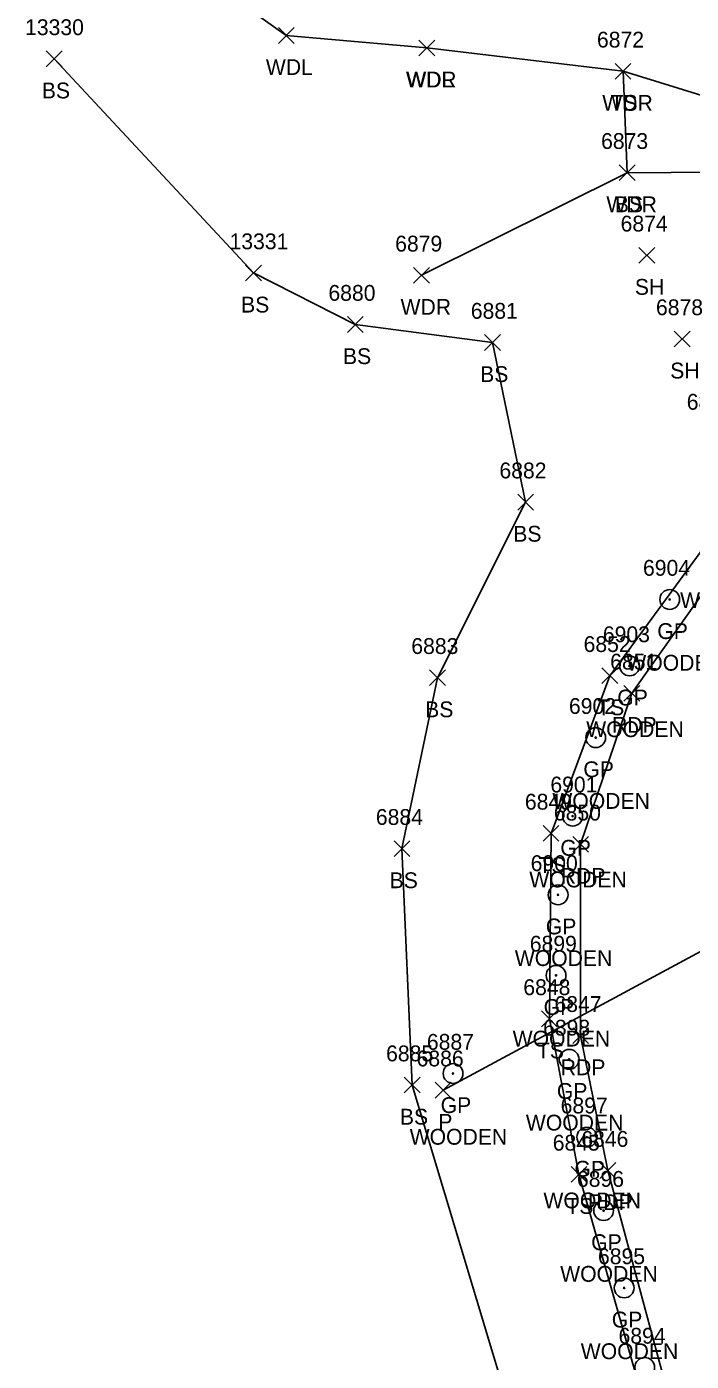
# Model space of a CAD drawing. Extents: x 1769141 to 1770817, y 735471 to 742405.
# Drawn here: x 1770005.7 to 1770089.7, y 740809.3 to 740978 of the extents above; entities that cross this region are included whole.
import ezdxf

# ---------------------------------------------------------------- set-up
doc = ezdxf.new("R2010")
doc.units = 0
for name, color, linetype in [('D_A', 7, 'Continuous'), ('D_I', 7, 'Continuous'), ('D_TIC', 7, 'Continuous'), ('DCP', 7, 'Continuous'), ('L_A', 7, 'Continuous'), ('L_I', 7, 'Continuous'), ('L_TIC', 7, 'Continuous'), ('LAWA', 7, 'Continuous'), ('LELB', 7, 'Continuous'), ('P_A', 7, 'Continuous'), ('P_I', 7, 'Continuous'), ('P_TIC', 7, 'Continuous'), ('PET', 7, 'Continuous'), ('R_A', 7, 'Continuous'), ('R_C', 7, 'Continuous'), ('R_I', 7, 'Continuous'), ('RGP', 7, 'Continuous')]:
    doc.layers.add(name, color=color, linetype=linetype)

msp = doc.modelspace()

# ---------------------------------------------------------------- linework, layer by layer
at = {"layer": 'D_TIC'}
for points in [[(1770057.36, 740842.55), (1770059.36, 740844.55)], [(1770059.36, 740842.55), (1770057.36, 740844.55)]]:
    msp.add_lwpolyline(points, dxfattribs=at)
at = {"layer": 'DCP'}
msp.add_lwpolyline([(1770123.5, 740878.66), (1770058.36, 740843.55)], dxfattribs=at)
at = {"layer": 'L_TIC'}
for points in [[(1770037.53, 740975.89), (1770039.53, 740977.89)], [(1770039.53, 740975.89), (1770037.53, 740977.89)], [(1770055.29, 740974.31), (1770057.29, 740976.31)], [(1770057.29, 740974.31), (1770055.29, 740976.31)], [(1770055.29, 740974.31), (1770057.29, 740976.31)], [(1770057.29, 740974.31), (1770055.29, 740976.31)], [(1770008.18, 740972.93), (1770010.18, 740974.93)], [(1770010.18, 740972.93), (1770008.18, 740974.93)], [(1770080.1, 740971.36), (1770082.1, 740973.36)], [(1770082.1, 740971.36), (1770080.1, 740973.36)], [(1770080.1, 740971.36), (1770082.1, 740973.36)], [(1770082.1, 740971.36), (1770080.1, 740973.36)], [(1770080.62, 740958.54), (1770082.62, 740960.54)], [(1770082.62, 740958.54), (1770080.62, 740960.54)], [(1770080.62, 740958.54), (1770082.62, 740960.54)], [(1770082.62, 740958.54), (1770080.62, 740960.54)], [(1770083.1, 740948.1), (1770085.1, 740950.1)], [(1770085.1, 740948.1), (1770083.1, 740950.1)], [(1770033.37, 740945.86), (1770035.37, 740947.86)], [(1770035.37, 740945.86), (1770033.37, 740947.86)], [(1770054.61, 740945.57), (1770056.61, 740947.57)], [(1770056.61, 740945.57), (1770054.61, 740947.57)], [(1770046.25, 740939.34), (1770048.25, 740941.34)], [(1770048.25, 740939.34), (1770046.25, 740941.34)], [(1770063.59, 740937.07), (1770065.59, 740939.07)], [(1770065.59, 740937.07), (1770063.59, 740939.07)], [(1770087.57, 740937.52), (1770089.57, 740939.52)], [(1770089.57, 740937.52), (1770087.57, 740939.52)], [(1770067.78, 740916.89), (1770069.78, 740918.89)], [(1770069.78, 740916.89), (1770067.78, 740918.89)], [(1770078.42, 740894.94), (1770080.42, 740896.94)], [(1770080.42, 740894.94), (1770078.42, 740896.94)], [(1770056.64, 740894.69), (1770058.64, 740896.69)], [(1770058.64, 740894.69), (1770056.64, 740896.69)], [(1770071, 740875.01), (1770073, 740877.01)], [(1770073, 740875.01), (1770071, 740877.01)], [(1770052.15, 740873.08), (1770054.15, 740875.08)], [(1770054.15, 740873.08), (1770052.15, 740875.08)], [(1770070.79, 740851.56), (1770072.79, 740853.56)], [(1770072.79, 740851.56), (1770070.79, 740853.56)], [(1770053.44, 740843.19), (1770055.44, 740845.19)], [(1770055.44, 740843.19), (1770053.44, 740845.19)], [(1770074.52, 740831.9), (1770076.52, 740833.9)], [(1770076.52, 740831.9), (1770074.52, 740833.9)]]:
    msp.add_lwpolyline(points, dxfattribs=at)
at = {"layer": 'LAWA'}
for points in [[(1770038.53, 740976.89), (1770014.41, 740994.02)], [(1770056.29, 740975.31), (1770038.53, 740976.89)], [(1770056.29, 740975.31), (1770081.1, 740972.36), (1770081.62, 740959.54), (1770055.61, 740946.57)]]:
    msp.add_lwpolyline(points, dxfattribs=at)
at = {"layer": 'LELB'}
for points in [[(1770102.49, 740709.21), (1770094.87, 740758.44), (1770085.33, 740798.47), (1770075.52, 740832.9), (1770071.79, 740852.56), (1770072, 740876.01), (1770079.42, 740895.94), (1770093.05, 740914.5), (1770103.42, 740925.63), (1770113.67, 740937.45), (1770115.5, 740958.52), (1770111.47, 740971.26), (1770103.86, 740991.31), (1770100.12, 740990.08), (1770106.06, 740964.67), (1770081.1, 740972.36)], [(1770009.18, 740973.93), (1770034.37, 740946.86)], [(1770108.22, 740970.65), (1770109.46, 740959.73), (1770081.62, 740959.54)], [(1770047.25, 740940.34), (1770034.37, 740946.86)], [(1770047.25, 740940.34), (1770064.59, 740938.07), (1770068.78, 740917.89), (1770057.64, 740895.69), (1770053.15, 740874.08), (1770054.44, 740844.19)], [(1770054.44, 740844.19), (1770066.7, 740803.36)]]:
    msp.add_lwpolyline(points, dxfattribs=at)
at = {"layer": 'P_TIC'}
for points in [[(1770081.21, 740892.72), (1770083.21, 740894.72)], [(1770083.21, 740892.72), (1770081.21, 740894.72)], [(1770074.74, 740873.63), (1770076.74, 740875.63)], [(1770076.74, 740873.63), (1770074.74, 740875.63)], [(1770074.73, 740849.43), (1770076.73, 740851.43)], [(1770076.73, 740849.43), (1770074.73, 740851.43)], [(1770078.18, 740832.38), (1770080.18, 740834.38)], [(1770080.18, 740832.38), (1770078.18, 740834.38)]]:
    msp.add_lwpolyline(points, dxfattribs=at)
at = {"layer": 'PET'}
msp.add_lwpolyline([(1770105.13, 740709.72), (1770097.35, 740759.47), (1770088.63, 740798.34), (1770079.18, 740833.38), (1770075.73, 740850.43), (1770075.74, 740874.63), (1770082.21, 740893.72), (1770094.91, 740911.6)], dxfattribs=at)
at = {"layer": 'RGP'}
for p, q in [((1770087, 740905.58), (1770087, 740905.58)), ((1770081.93, 740897.18), (1770081.93, 740897.18)), ((1770077.64, 740888.11), (1770077.64, 740888.11)), ((1770074.73, 740878.18), (1770074.73, 740878.18)), ((1770072.89, 740868.24), (1770072.89, 740868.24)), ((1770072.63, 740858.06), (1770072.63, 740858.06)), ((1770074.29, 740847.44), (1770074.29, 740847.44)), ((1770059.61, 740845.65), (1770059.61, 740845.65)), ((1770076.52, 740837.6), (1770076.52, 740837.6)), ((1770078.64, 740828.32), (1770078.64, 740828.32)), ((1770081.24, 740818.54), (1770081.24, 740818.54))]:
    msp.add_line(p, q, dxfattribs=at)
for centre, radius in [((1770087, 740905.58), 1.25), ((1770087, 740905.58), 0.0833), ((1770081.93, 740897.18), 1.25), ((1770081.93, 740897.18), 0.0833), ((1770077.64, 740888.11), 1.25), ((1770077.64, 740888.11), 0.0833), ((1770074.73, 740878.18), 1.25), ((1770074.73, 740878.18), 0.0833), ((1770072.89, 740868.24), 1.25), ((1770072.89, 740868.24), 0.0833), ((1770072.63, 740858.06), 1.25), ((1770072.63, 740858.06), 0.0833), ((1770074.29, 740847.44), 1.25), ((1770059.61, 740845.65), 1.25), ((1770074.29, 740847.44), 0.0833), ((1770059.61, 740845.65), 0.0833), ((1770076.52, 740837.6), 1.25), ((1770076.52, 740837.6), 0.0833), ((1770078.64, 740828.32), 1.25), ((1770078.64, 740828.32), 0.0833), ((1770081.24, 740818.54), 1.25), ((1770081.24, 740818.54), 0.0833), ((1770083.84, 740808.49), 1.25)]:
    msp.add_circle(centre, radius, dxfattribs=at)

# ---------------------------------------------------------------- texts
at = {"layer": 'D_A'}
msp.add_text('P', height=2, dxfattribs=at).set_placement((1770057.74, 740838.55))
at = {"layer": 'D_I'}
msp.add_text('6886', height=2, dxfattribs=at).set_placement((1770055, 740846.55))
at = {"layer": 'L_A'}
for s, p in [('WDL', (1770035.94, 740971.89)), ('BS', (1770007.62, 740968.93)), ('WDR', (1770053.65, 740970.31)), ('WDL', (1770053.71, 740970.31)), ('WDR', (1770078.47, 740967.36)), ('TS', (1770079.51, 740967.36)), ('WDR', (1770078.99, 740954.54)), ('BS', (1770080.06, 740954.54)), ('SH', (1770082.59, 740944.1)), ('BS', (1770032.81, 740941.86)), ('WDR', (1770052.97, 740941.57)), ('BS', (1770045.69, 740935.34)), ('SH', (1770087.06, 740933.52)), ('BS', (1770063.03, 740933.07)), ('BS', (1770067.22, 740912.89)), ('BS', (1770056.08, 740890.69)), ('TS', (1770077.83, 740890.94)), ('TS', (1770070.41, 740871.01)), ('BS', (1770051.59, 740869.08)), ('TS', (1770070.2, 740847.56)), ('BS', (1770052.89, 740839.19)), ('TS', (1770073.93, 740827.9))]:
    msp.add_text(s, height=2, dxfattribs=at).set_placement(p)
at = {"layer": 'L_I'}
for s, p in [('13330', (1770005.5, 740976.93)), ('6872', (1770077.8, 740975.36)), ('6872', (1770077.8, 740975.36)), ('6873', (1770078.32, 740962.54)), ('6873', (1770078.32, 740962.54)), ('6874', (1770080.79, 740952.1)), ('13331', (1770031.35, 740949.86)), ('6879', (1770052.29, 740949.57)), ('6880', (1770043.85, 740943.34)), ('6881', (1770061.85, 740941.07)), ('6878', (1770085.26, 740941.52)), ('6877', (1770089.15, 740929.57)), ('6882', (1770065.47, 740920.89)), ('6883', (1770054.33, 740898.69)), ('6852', (1770076.11, 740898.94)), ('6849', (1770068.69, 740879.01)), ('6884', (1770049.85, 740877.08)), ('6848', (1770068.49, 740855.56)), ('6885', (1770051.14, 740847.19)), ('6845', (1770072.21, 740835.9))]:
    msp.add_text(s, height=2, dxfattribs=at).set_placement(p)
at = {"layer": 'P_A'}
for p in [(1770079.7, 740888.72), (1770073.23, 740869.63), (1770073.22, 740845.43), (1770076.67, 740828.38)]:
    msp.add_text('RDP', height=2, dxfattribs=at).set_placement(p)
at = {"layer": 'P_I'}
for s, p in [('6851', (1770079.47, 740896.72)), ('6850', (1770072.35, 740877.63)), ('6847', (1770072.43, 740853.43)), ('6846', (1770075.82, 740836.38))]:
    msp.add_text(s, height=2, dxfattribs=at).set_placement(p)
at = {"layer": 'R_A'}
for p in [(1770085.43, 740900.58), (1770080.37, 740892.18), (1770076.08, 740883.11), (1770073.17, 740873.18), (1770071.33, 740863.24), (1770071.06, 740853.06), (1770072.73, 740842.44), (1770058.04, 740840.65), (1770074.95, 740832.6), (1770077.07, 740823.32), (1770079.67, 740813.54)]:
    msp.add_text('GP', height=2, dxfattribs=at).set_placement(p)
at = {"layer": 'R_C'}
for p in [(1770088.31, 740904.49), (1770081.51, 740896.58), (1770076.44, 740888.18), (1770072.16, 740879.11), (1770069.24, 740869.18), (1770067.41, 740859.24), (1770067.14, 740849.06), (1770068.81, 740838.44), (1770054.12, 740836.65), (1770071.03, 740828.6), (1770073.15, 740819.32), (1770075.75, 740809.54)]:
    msp.add_text('WOODEN', height=2, dxfattribs=at).set_placement(p)
at = {"layer": 'R_I'}
for s, p in [('6904', (1770083.62, 740908.58)), ('6903', (1770078.55, 740900.18)), ('6902', (1770074.26, 740891.11)), ('6901', (1770071.91, 740881.18)), ('6900', (1770069.42, 740871.24)), ('6899', (1770069.31, 740861.06)), ('6898', (1770070.99, 740850.44)), ('6887', (1770056.3, 740848.65)), ('6897', (1770073.21, 740840.6)), ('6896', (1770075.27, 740831.32)), ('6895', (1770077.93, 740821.54)), ('6894', (1770080.53, 740811.49))]:
    msp.add_text(s, height=2, dxfattribs=at).set_placement(p)

doc.saveas('drawing.dxf')
